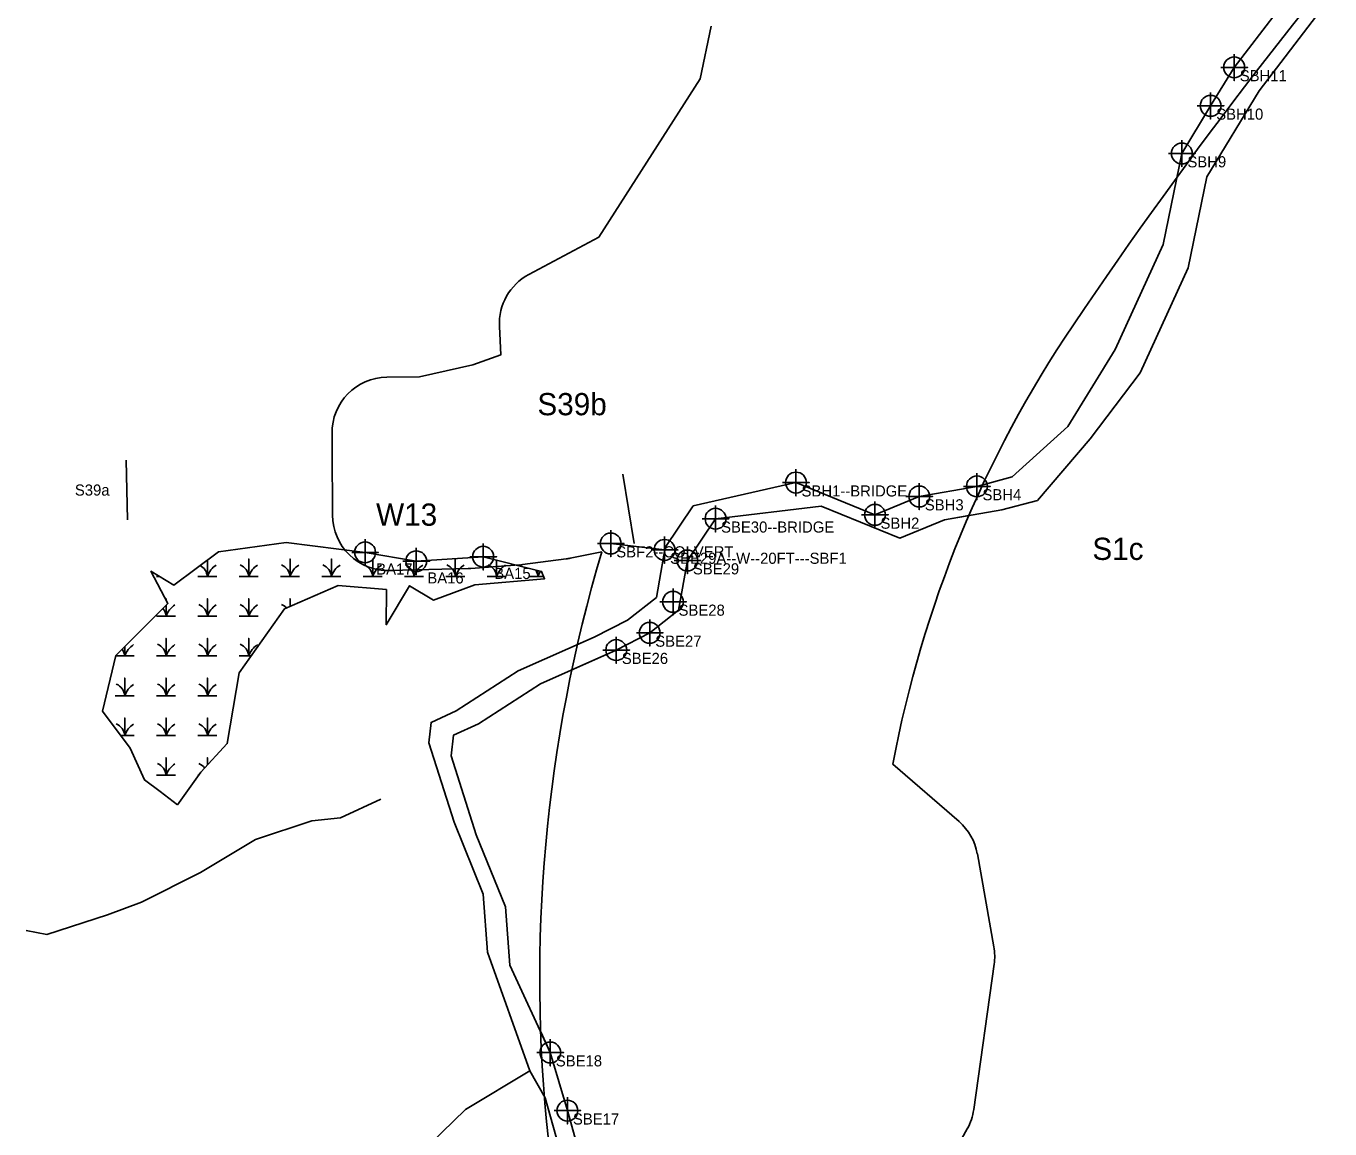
# Model space of a CAD drawing. Extents: x 1253697 to 1278588, y 912189 to 981699.
# Drawn here: x 1260893 to 1262066, y 931037 to 932030 of the extents above; entities that cross this region are included whole.
import ezdxf

# ---------------------------------------------------------------- set-up
doc = ezdxf.new("R2010")
doc.units = 0
for name, color, linetype in [('Default', 7, 'Continuous'), ('Exist Environmental Wetland Boundary', 7, 'Continuous'), ('Exist Environmental Wetland Boundary Cogo Comment', 7, 'Continuous'), ('Exist Environmental Wetland Boundary Cogo Number', 7, 'Continuous'), ('Exist Environmental Wetland Boundary Cogo Point CELL', 7, 'Continuous'), ('Exist Hydro Jurisdictional Stream or Body of Water Mitigable', 7, 'Continuous'), ('Exist Hydro Jurisdictional Stream or Body of Water Mitigable Cogo Comment', 7, 'Continuous'), ('Exist Hydro Jurisdictional Stream or Body of Water Mitigable Cogo Number', 7, 'Continuous'), ('Exist Hydro Jurisdictional Stream or Body of Water Mitigable Cogo Point CELL', 7, 'Continuous')]:
    doc.layers.add(name, color=color, linetype=linetype)

msp = doc.modelspace()

# ---------------------------------------------------------------- linework, layer by layer
at = {"layer": 'Default'}
for p, q in [((1261429.9, 931626.4), (1261440.2, 931563.8)), ((1261382.6, 931550.7), (1261411, 931556.5)), ((1261382.6, 931550.7), (1261411, 931556.5)), ((1261382.6, 931550.7), (1261411, 931556.5)), ((1261382.6, 931550.7), (1261411, 931556.5)), ((1261293.1, 931541.4), (1261336.6, 931544.6)), ((1261293.1, 931541.4), (1261336.6, 931544.6)), ((1261293.1, 931541.4), (1261336.6, 931544.6)), ((1261293.1, 931541.4), (1261336.6, 931544.6)), ((1261339.5, 931544.9), (1261379, 931550.1)), ((1261339.5, 931544.9), (1261379, 931550.1)), ((1261339.5, 931544.9), (1261379, 931550.1)), ((1261339.5, 931544.9), (1261379, 931550.1)), ((1261219.9, 931539.5), (1261290.8, 931541.3)), ((1261219.9, 931539.5), (1261290.8, 931541.3)), ((1261219.9, 931539.5), (1261290.8, 931541.3)), ((1261219.9, 931539.5), (1261290.8, 931541.3)), ((1261763.9, 931201), (1261749.1, 931284.7)), ((1261763.9, 931201), (1261749.1, 931284.7)), ((1261763.9, 931201), (1261749.1, 931284.7)), ((1261763.9, 931201), (1261749.1, 931284.7)), ((1261745.8, 931054.5), (1261764.2, 931185.2)), ((1261745.8, 931054.5), (1261764.2, 931185.2)), ((1261745.8, 931054.5), (1261764.2, 931185.2)), ((1261745.8, 931054.5), (1261764.2, 931185.2)), ((1261719.9, 931001.2), (1261739.9, 931037)), ((1261719.9, 931001.2), (1261739.9, 931037)), ((1261719.9, 931001.2), (1261739.9, 931037)), ((1261719.9, 931001.2), (1261739.9, 931037))]:
    msp.add_line(p, q, dxfattribs=at)
for points in [[(1261509.3, 932029.5), (1261499.4, 931982.2), (1261408.2, 931839.7), (1261345.2, 931805.9)], [(1261509.3, 932029.5), (1261499.4, 931982.2), (1261408.2, 931839.7), (1261345.2, 931805.9)], [(1261509.3, 932029.5), (1261499.4, 931982.2), (1261408.2, 931839.7), (1261345.2, 931805.9)], [(1261509.3, 932029.5), (1261499.4, 931982.2), (1261408.2, 931839.7), (1261345.2, 931805.9)], [(1261318.9, 931759.3), (1261320.2, 931733.7), (1261295, 931724.6), (1261247, 931714), (1261217.5, 931713.6)], [(1261318.9, 931759.3), (1261320.2, 931733.7), (1261295, 931724.6), (1261247, 931714), (1261217.5, 931713.6)], [(1261318.9, 931759.3), (1261320.2, 931733.7), (1261295, 931724.6), (1261247, 931714), (1261217.5, 931713.6)], [(1261318.9, 931759.3), (1261320.2, 931733.7), (1261295, 931724.6), (1261247, 931714), (1261217.5, 931713.6)], [(1261168.1, 931663.1), (1261168.3, 931649.1), (1261168.6, 931589.2)], [(1261168.1, 931663.1), (1261168.3, 931649.1), (1261168.6, 931589.2)], [(1261168.1, 931663.1), (1261168.3, 931649.1), (1261168.6, 931589.2)], [(1261168.1, 931663.1), (1261168.3, 931649.1), (1261168.6, 931589.2)], [(1261732.6, 931313.7), (1261673.1, 931365.3), (1261673, 931365.5)], [(1261732.6, 931313.7), (1261673.1, 931365.3), (1261673, 931365.5)], [(1261732.6, 931313.7), (1261673.1, 931365.3), (1261673, 931365.5)], [(1261732.6, 931313.7), (1261673.1, 931365.3), (1261673, 931365.5)]]:
    msp.add_lwpolyline(points, dxfattribs=at)
for centre, radius, start, end in [((1265603.7, 929210.6), 4550, 131.7354, 145.9116), ((1265603.7, 929210.6), 4550, 131.7354, 145.9116), ((1265603.7, 929210.6), 4550, 131.7354, 145.9116), ((1265603.7, 929210.6), 4550, 131.7354, 145.9116), ((1261368.8, 931761.8), 50, 118.179, 182.8582), ((1261368.8, 931761.8), 50, 118.179, 182.8582), ((1261368.8, 931761.8), 50, 118.179, 182.8582), ((1261368.8, 931761.8), 50, 118.179, 182.8582), ((1262705.1, 931172.2), 1050, 145.9116, 169.3956), ((1262705.1, 931172.2), 1050, 145.9116, 169.3956), ((1262705.1, 931172.2), 1050, 145.9116, 169.3956), ((1262705.1, 931172.2), 1050, 145.9116, 169.3956), ((1261218.1, 931663.6), 50, 90.6805, 180.6805), ((1261218.1, 931663.6), 50, 90.6805, 180.6805), ((1261218.1, 931663.6), 50, 90.6805, 180.6805), ((1261218.1, 931663.6), 50, 90.6805, 180.6805), ((1261218.6, 931589.5), 50, 180.2894, 271.4797), ((1261218.6, 931589.5), 50, 180.2894, 271.4797), ((1261218.6, 931589.5), 50, 180.2894, 271.4797), ((1261218.6, 931589.5), 50, 180.2894, 271.4797), ((1262705.1, 931172.2), 1350, 163.4618, 208.8651), ((1262705.1, 931172.2), 1350, 163.4618, 208.8651), ((1262705.1, 931172.2), 1350, 163.4618, 208.8651), ((1262705.1, 931172.2), 1350, 163.4618, 208.8651), ((1261333, 931594.4), 50, 274.109, 277.4811), ((1261333, 931594.4), 50, 274.109, 277.4811), ((1261333, 931594.4), 50, 274.109, 277.4811), ((1261333, 931594.4), 50, 274.109, 277.4811), ((1261372.5, 931599.6), 50, 277.4811, 281.6997), ((1261372.5, 931599.6), 50, 277.4811, 281.6997), ((1261372.5, 931599.6), 50, 277.4811, 281.6997), ((1261372.5, 931599.6), 50, 277.4811, 281.6997), ((1261289.5, 931591.3), 50, 271.4797, 274.109), ((1261289.5, 931591.3), 50, 271.4797, 274.109), ((1261289.5, 931591.3), 50, 271.4797, 274.109), ((1261289.5, 931591.3), 50, 271.4797, 274.109), ((1261699.8, 931275.9), 50, 10.0723, 49.0457), ((1261699.8, 931275.9), 50, 10.0723, 49.0457), ((1261699.8, 931275.9), 50, 10.0723, 49.0457), ((1261699.8, 931275.9), 50, 10.0723, 49.0457), ((1261714.7, 931192.2), 50, 351.9693, 10.0723), ((1261714.7, 931192.2), 50, 351.9693, 10.0723), ((1261714.7, 931192.2), 50, 351.9693, 10.0723), ((1261714.7, 931192.2), 50, 351.9693, 10.0723), ((1261696.3, 931061.4), 50, 330.7998, 351.9693), ((1261696.3, 931061.4), 50, 330.7998, 351.9693), ((1261696.3, 931061.4), 50, 330.7998, 351.9693), ((1261696.3, 931061.4), 50, 330.7998, 351.9693)]:
    msp.add_arc(centre, radius, start, end, dxfattribs=at)
at = {"layer": 'Exist Environmental Wetland Boundary'}
msp.add_lwpolyline([(1261028.9, 931328.8), (1261013.4, 931340.6), (1260999.4, 931351.2), (1260986.3, 931379.8), (1260961.5, 931413.1), (1260973.6, 931463.2), (1261020.3, 931510), (1261005, 931538.9), (1261025.8, 931526.5), (1261065.8, 931556.5), (1261126.9, 931564.7), (1261197.9, 931555.9), (1261243.9, 931547.9), (1261304.2, 931552), (1261356.8, 931538.7), (1261359.5, 931532.2), (1261296.6, 931526.7), (1261259.5, 931513), (1261238, 931525.9), (1261217, 931490.8), (1261217.1, 931522.4), (1261173.5, 931526), (1261125.4, 931505), (1261084.6, 931447.6), (1261073.8, 931383.9), (1261049.9, 931358.2)], close=True, dxfattribs=at)
at = {"layer": 'Exist Environmental Wetland Boundary Cogo Point CELL'}
for points in [[(1261197.9, 931567.9), (1261197.9, 931543.9), (1261197.9, 931555.9), (1261209.9, 931555.9), (1261185.9, 931555.9)], [(1261243.9, 931559.9), (1261243.9, 931535.9), (1261243.9, 931547.9), (1261255.9, 931547.9), (1261231.9, 931547.9)], [(1261304.2, 931564), (1261304.2, 931540), (1261304.2, 931552), (1261316.2, 931552), (1261292.2, 931552)]]:
    msp.add_lwpolyline(points, dxfattribs=at)
for centre in [(1261197.9, 931555.9), (1261243.9, 931547.9), (1261304.2, 931552)]:
    msp.add_circle(centre, 9.38, dxfattribs=at)
at = {"layer": 'Exist Hydro Jurisdictional Stream or Body of Water Mitigable'}
for p, q in [((1260982.9, 931639), (1260983.9, 931585.1)), ((1261467.5, 931558.1), (1261419, 931563.9)), ((1261010.1, 931534.2), (1261012.8, 931534.2)), ((1261047.3, 931355.3), (1261047.8, 931355.3))]:
    msp.add_line(p, q, dxfattribs=at)
for points in [[(1261748.7, 931615.3), (1261780.5, 931623.8), (1261830.5, 931669.2), (1261873.2, 931738.6), (1261916.3, 931833), (1261933.2, 931914.9), (1261959.1, 931957.8), (1261980.3, 931992.4), (1262031.9, 932059.9), (1262109.4, 932158.6), (1262157.6, 932182.7), (1262202.1, 932235.8), (1262220.1, 932256.4), (1262262, 932266.8), (1262325.5, 932261.6), (1262401.7, 932224.7), (1262486.7, 932218.7), (1262521.3, 932227), (1262531.2, 932249.7), (1262554.1, 932254), (1262598.9, 932243.6), (1262661.1, 932274.4), (1262754.4, 932295.4), (1262783.4, 932291.7)], [(1262763.8, 932271.3), (1262683.6, 932253.3), (1262601, 932218.3), (1262576.7, 932232.9), (1262553.8, 932228.6), (1262548.5, 932205.6), (1262509.2, 932197.6), (1262424.2, 932203.6), (1262348.1, 932240.5), (1262284.6, 932245.7), (1262242.7, 932235.3), (1262180.2, 932161.6), (1262131.9, 932137.5), (1262054.4, 932038.8), (1262002.9, 931971.3), (1261955.7, 931893.8), (1261938.9, 931811.9), (1261895.8, 931717.5), (1261850.7, 931658.2), (1261803.1, 931602.7), (1261771.2, 931594.2), (1261719.4, 931585.1)], [(1261389, 931472.9), (1261404, 931479.5), (1261434, 931495), (1261460.1, 931515.4), (1261467.9, 931560.2), (1261493.3, 931597.7), (1261585.8, 931618.7)], [(1261585.8, 931618.7), (1261656.9, 931589.7), (1261696.8, 931606.2), (1261748.7, 931615.3), (1261753.8, 931616.7)], [(1261384, 931450.2), (1261424, 931468), (1261454.1, 931483.5), (1261480.1, 931503.9), (1261488, 931548.6), (1261513.4, 931586.2), (1261608.4, 931597.6)], [(1261608.4, 931597.6), (1261679.4, 931568.7), (1261719.4, 931585.1), (1261741.4, 931589)], [(1261047.3, 931534.2), (1261055.9, 931534.2), (1261055.9, 931549.1)], [(1261055.9, 931549.1), (1261055.9, 931534.2), (1261064.5, 931534.2)], [(1261084.5, 931534.2), (1261093.1, 931534.2), (1261093.1, 931550), (1261093.1, 931534.2), (1261101.7, 931534.2)], [(1261121.7, 931534.2), (1261130.3, 931534.2), (1261130.3, 931550), (1261130.3, 931534.2), (1261138.9, 931534.2)], [(1261158.9, 931534.2), (1261167.5, 931534.2), (1261167.5, 931550), (1261167.5, 931534.2), (1261176.1, 931534.2)], [(1261196.1, 931534.2), (1261204.7, 931534.2), (1261204.7, 931550), (1261204.7, 931534.2), (1261213.3, 931534.2)], [(1261233.3, 931534.2), (1261241.9, 931534.2), (1261241.9, 931548.3)], [(1261241.9, 931548.3), (1261241.9, 931534.2), (1261250.5, 931534.2)], [(1261270.5, 931534.2), (1261279.1, 931534.2), (1261279.1, 931550), (1261279.1, 931534.2), (1261287.7, 931534.2)], [(1261307.7, 931534.2), (1261316.3, 931534.2), (1261316.3, 931549)], [(1261316.3, 931549), (1261316.3, 931534.2), (1261324.9, 931534.2)], [(1261344.9, 931534.2), (1261353.5, 931534.2), (1261353.5, 931539.6)], [(1261353.5, 931539.6), (1261353.5, 931534.2), (1261358.7, 931534.2)], [(1261010.1, 931498.5), (1261018.7, 931498.5), (1261018.7, 931508.3)], [(1261018.7, 931513.1), (1261018.7, 931514.2), (1261018.7, 931513.1)], [(1261018.7, 931508.3), (1261018.7, 931498.5), (1261027.3, 931498.5)], [(1261047.3, 931498.5), (1261055.9, 931498.5), (1261055.9, 931514.2), (1261055.9, 931498.5), (1261064.5, 931498.5)], [(1261084.5, 931498.5), (1261093.1, 931498.5), (1261093.1, 931514.2), (1261093.1, 931498.5), (1261101.7, 931498.5)], [(1261130.3, 931507.2), (1261130.3, 931514.2), (1261130.3, 931507.2)], [(1261010.1, 931462.7), (1261018.7, 931462.7), (1261018.7, 931478.5), (1261018.7, 931462.7), (1261027.3, 931462.7)], [(1261047.3, 931462.7), (1261055.9, 931462.7), (1261055.9, 931478.5), (1261055.9, 931462.7), (1261064.5, 931462.7)], [(1261084.5, 931462.7), (1261093.1, 931462.7), (1261093.1, 931478.5), (1261093.1, 931462.7), (1261095.3, 931462.7)], [(1261359.9, 931065.1), (1261346.3, 931089.4), (1261308.2, 931196.1), (1261304.2, 931248.4), (1261278, 931313.2), (1261255.4, 931384.4), (1261257.3, 931402.9), (1261280, 931413.2), (1261335.6, 931449.2), (1261404, 931479.5)], [(1260973.5, 931462.7), (1260981.5, 931462.7), (1260981.5, 931471)], [(1260981.5, 931471), (1260981.5, 931462.7), (1260990.1, 931462.7)], [(1261364.6, 931105.8), (1261328.3, 931184.5), (1261324.3, 931236.8), (1261298, 931301.6), (1261275.4, 931372.8), (1261277.4, 931391.4), (1261300.1, 931401.6), (1261355.7, 931437.6), (1261424, 931468)], [(1260972.9, 931426.9), (1260981.5, 931426.9), (1260981.5, 931442.7), (1260981.5, 931426.9), (1260990.1, 931426.9)], [(1261010.1, 931426.9), (1261018.7, 931426.9), (1261018.7, 931442.7), (1261018.7, 931426.9), (1261027.3, 931426.9)], [(1261047.3, 931426.9), (1261055.9, 931426.9), (1261055.9, 931442.7), (1261055.9, 931426.9), (1261064.5, 931426.9)], [(1260977.9, 931391.1), (1260981.5, 931391.1), (1260981.5, 931406.9), (1260981.5, 931391.1), (1260990.1, 931391.1)], [(1261010.1, 931391.1), (1261018.7, 931391.1), (1261018.7, 931406.9), (1261018.7, 931391.1), (1261027.3, 931391.1)], [(1261047.3, 931391.1), (1261055.9, 931391.1), (1261055.9, 931406.9), (1261055.9, 931391.1), (1261064.5, 931391.1)], [(1261010.1, 931355.3), (1261018.7, 931355.3), (1261018.7, 931371.1), (1261018.7, 931355.3), (1261027.3, 931355.3)], [(1261055.9, 931364.7), (1261055.9, 931371.1), (1261055.9, 931364.7)], [(1261212.1, 931333.7), (1261175.6, 931317), (1261149.8, 931314.4), (1261099.1, 931297.6), (1261049.7, 931267.8), (1260996.5, 931241.2), (1260966.1, 931229.6), (1260911.4, 931212.1), (1260892.7, 931215.6)], [(1261572.5, 930442.5), (1261571.3, 930446.9), (1261539.4, 930524.6), (1261536.8, 930534.2), (1261517.1, 930590), (1261492.5, 930637.6), (1261494.2, 930645.3), (1261473.8, 930699.8), (1261474.9, 930733.5), (1261460.8, 930790.3), (1261436.9, 930842.9), (1261424.6, 930901.5), (1261406.6, 930958.3), (1261380, 931053.5), (1261364.6, 931105.8), (1261356, 931124.5)], [(1261346.3, 931089.4), (1261288.3, 931054.6), (1261256.5, 931023.7), (1261210.5, 930997.2), (1261187.1, 930986.9), (1261163.6, 930986), (1261166.4, 930962), (1261162.5, 930933), (1261156.7, 930900.6), (1261137.1, 930848.8), (1261108.5, 930825.1), (1261079.7, 930792.5), (1261059.7, 930755.4), (1261063.9, 930720.4), (1261042.9, 930702.5), (1260974.6, 930686.1)], [(1261533.2, 930504.2), (1261516.7, 930545.8), (1261497, 930601.6), (1261472.4, 930649.2), (1261453.7, 930711.4), (1261454.8, 930745), (1261440.7, 930801.9), (1261416.8, 930854.5), (1261404.6, 930913), (1261386.6, 930969.8), (1261359.9, 931065.1), (1261359.3, 931066.1)]]:
    msp.add_lwpolyline(points, dxfattribs=at)
for centre, radius, start, end in [((1261043.6, 931533.3), 12.3, 4.1403, 62.0658), ((1261074.1, 931528.2), 19.2, 122.1274, 161.6222), ((1261080.8, 931533.3), 12.3, 4.1403, 67.535), ((1261111.3, 931528.2), 19.2, 122.1274, 161.6222), ((1261118, 931533.3), 12.3, 4.1403, 67.535), ((1261148.5, 931528.2), 19.2, 122.1274, 161.6222), ((1261155.2, 931533.3), 12.3, 4.1403, 67.535), ((1261185.7, 931528.2), 19.2, 122.1274, 161.6222), ((1261192.4, 931533.3), 12.3, 4.1403, 67.535), ((1261222.9, 931528.2), 19.2, 122.1274, 161.6222), ((1261229.6, 931533.3), 12.3, 4.1403, 67.535), ((1261260.1, 931528.2), 19.2, 122.1274, 161.6222), ((1261266.8, 931533.3), 12.3, 4.1403, 67.535), ((1261297.3, 931528.2), 19.2, 122.1274, 161.6222), ((1261304, 931533.3), 12.3, 4.1403, 67.535), ((1261334.5, 931528.2), 19.2, 122.1274, 161.6222), ((1261341.2, 931533.3), 12.3, 4.1403, 33.189), ((1261371.7, 931528.2), 19.2, 145.7744, 161.6222), ((1261036.9, 931492.4), 19.2, 122.1274, 161.6222), ((1261043.6, 931497.6), 12.3, 4.1403, 67.535), ((1261074.1, 931492.4), 19.2, 122.1274, 161.6222), ((1261080.8, 931497.6), 12.3, 4.1403, 67.535), ((1261111.3, 931492.4), 19.2, 122.1274, 161.6222), ((1261118, 931497.6), 12.3, 41.9914, 67.535), ((1261006.4, 931497.6), 12.3, 4.1403, 39.8933), ((1260999.7, 931456.6), 19.2, 122.1274, 161.6222), ((1261006.4, 931461.8), 12.3, 4.1403, 67.535), ((1261036.9, 931456.6), 19.2, 122.1274, 161.6222), ((1261043.6, 931461.8), 12.3, 4.1403, 67.535), ((1261074.1, 931456.6), 19.2, 122.1274, 161.6222), ((1261080.8, 931461.8), 12.3, 4.1403, 67.535), ((1261111.3, 931456.6), 19.2, 122.1274, 161.6222), ((1260969.2, 931461.8), 12.3, 4.1403, 35.0446), ((1260969.2, 931426), 12.3, 4.1403, 67.535), ((1260999.7, 931420.8), 19.2, 122.1274, 161.6222), ((1261006.4, 931426), 12.3, 4.1403, 67.535), ((1261036.9, 931420.8), 19.2, 122.1274, 161.6222), ((1261043.6, 931426), 12.3, 4.1403, 67.535), ((1261074.1, 931420.8), 19.2, 122.1274, 161.6222), ((1260969.2, 931390.2), 12.3, 4.1403, 67.535), ((1261006.4, 931390.2), 12.3, 4.1403, 67.535), ((1261043.6, 931390.2), 12.3, 4.1403, 67.535), ((1260999.7, 931385.1), 19.2, 122.1274, 161.6222), ((1261036.9, 931385.1), 19.2, 122.1274, 161.6222), ((1261074.1, 931385.1), 19.2, 122.1274, 161.6222), ((1261006.4, 931354.4), 12.3, 4.1403, 67.535), ((1261036.9, 931349.3), 19.2, 122.1274, 161.6222), ((1261043.6, 931354.4), 12.3, 37.7023, 67.535)]:
    msp.add_arc(centre, radius, start, end, dxfattribs=at)
at = {"layer": 'Exist Hydro Jurisdictional Stream or Body of Water Mitigable Cogo Point CELL'}
for points in [[(1261980.3, 932004.4), (1261980.3, 931980.4), (1261980.3, 931992.4), (1261992.3, 931992.4), (1261968.3, 931992.4)], [(1261959.1, 931969.8), (1261959.1, 931945.8), (1261959.1, 931957.8), (1261971.1, 931957.8), (1261947.1, 931957.8)], [(1261933.2, 931926.9), (1261933.2, 931902.9), (1261933.2, 931914.9), (1261945.2, 931914.9), (1261921.2, 931914.9)], [(1261585.8, 931630.7), (1261585.8, 931606.7), (1261585.8, 931618.7), (1261597.8, 931618.7), (1261573.8, 931618.7)], [(1261748.7, 931627.3), (1261748.7, 931603.3), (1261748.7, 931615.3), (1261760.7, 931615.3), (1261736.7, 931615.3)], [(1261696.8, 931618.2), (1261696.8, 931594.2), (1261696.8, 931606.2), (1261708.8, 931606.2), (1261684.8, 931606.2)], [(1261656.9, 931601.7), (1261656.9, 931577.7), (1261656.9, 931589.7), (1261668.9, 931589.7), (1261644.9, 931589.7)], [(1261513.4, 931598.2), (1261513.4, 931574.2), (1261513.4, 931586.2), (1261525.4, 931586.2), (1261501.4, 931586.2)], [(1261419, 931575.9), (1261419, 931551.9), (1261419, 931563.9), (1261431, 931563.9), (1261407, 931563.9)], [(1261467.5, 931570.1), (1261467.5, 931546.1), (1261467.5, 931558.1), (1261479.5, 931558.1), (1261455.5, 931558.1)], [(1261488, 931560.6), (1261488, 931536.6), (1261488, 931548.6), (1261500, 931548.6), (1261476, 931548.6)], [(1261475.1, 931523.4), (1261475.1, 931499.4), (1261475.1, 931511.4), (1261487.1, 931511.4), (1261463.1, 931511.4)], [(1261454.1, 931495.5), (1261454.1, 931471.5), (1261454.1, 931483.5), (1261466.1, 931483.5), (1261442.1, 931483.5)], [(1261424, 931480), (1261424, 931456), (1261424, 931468), (1261436, 931468), (1261412, 931468)], [(1261364.6, 931117.8), (1261364.6, 931093.8), (1261364.6, 931105.8), (1261376.6, 931105.8), (1261352.6, 931105.8)], [(1261380, 931065.5), (1261380, 931041.5), (1261380, 931053.5), (1261392, 931053.5), (1261368, 931053.5)]]:
    msp.add_lwpolyline(points, dxfattribs=at)
for centre in [(1261980.3, 931992.4), (1261959.1, 931957.8), (1261933.2, 931914.9), (1261585.8, 931618.7), (1261748.7, 931615.3), (1261696.8, 931606.2), (1261513.4, 931586.2), (1261656.9, 931589.7), (1261419, 931563.9), (1261467.5, 931558.1), (1261488, 931548.6), (1261475.1, 931511.4), (1261454.1, 931483.5), (1261424, 931468), (1261364.6, 931105.8), (1261380, 931053.5)]:
    msp.add_circle(centre, 9.38, dxfattribs=at)

# ---------------------------------------------------------------- texts
at = {"layer": 'Exist Environmental Wetland Boundary Cogo Comment'}
for s, p in [('BA17', (1261207.9, 931535.9)), ('BA16', (1261253.9, 931527.9)), ('BA15', (1261314.2, 931532))]:
    msp.add_text(s, height=10, dxfattribs=at).set_placement(p)
at = {"layer": 'Exist Environmental Wetland Boundary Cogo Number'}
msp.add_text('W13', height=20, dxfattribs=at).set_placement((1261207.8, 931579.9))
at = {"layer": 'Exist Hydro Jurisdictional Stream or Body of Water Mitigable'}
msp.add_text('S39a', height=10, dxfattribs=at).set_placement((1260936.6, 931607))
at = {"layer": 'Exist Hydro Jurisdictional Stream or Body of Water Mitigable Cogo Comment'}
for s, p in [('SBH11', (1261985.3, 931979.9)), ('SBH10', (1261964.1, 931945.3)), ('SBH9', (1261938.2, 931902.4)), ('SBH1--BRIDGE', (1261590.8, 931606.2)), ('SBH4', (1261753.7, 931602.8)), ('SBH3', (1261701.8, 931593.7)), ('SBE30--BRIDGE', (1261518.4, 931573.7)), ('SBH2', (1261661.9, 931577.2)), ('SBF2--COLVERT', (1261424, 931551.4)), ('SBE29A--W--20FT---SBF1', (1261472.5, 931545.6)), ('SBE29', (1261493, 931536.1)), ('SBE28', (1261480.1, 931498.9)), ('SBE27', (1261459.1, 931471)), ('SBE26', (1261429, 931455.5)), ('SBE18', (1261369.6, 931093.3)), ('SBE17', (1261385, 931041))]:
    msp.add_text(s, height=10, dxfattribs=at).set_placement(p)
at = {"layer": 'Exist Hydro Jurisdictional Stream or Body of Water Mitigable Cogo Number'}
for s, p in [('S39b', (1261353, 931679.3)), ('S1c', (1261852.6, 931549.1))]:
    msp.add_text(s, height=20, dxfattribs=at).set_placement(p)

doc.saveas('drawing.dxf')
